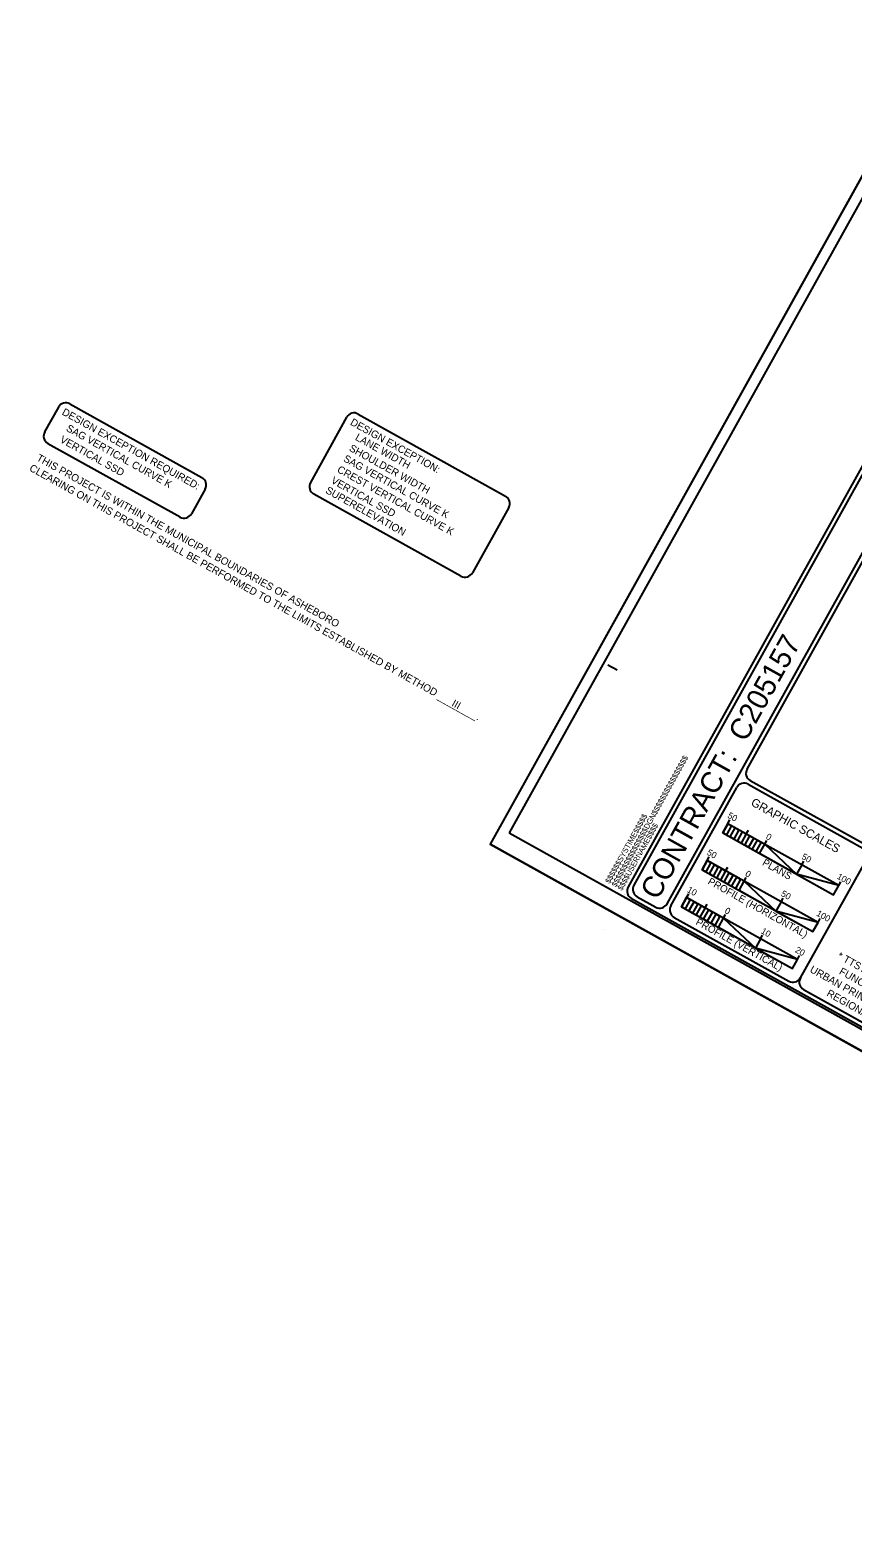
# Model space of a CAD drawing. Extents: x 1754939 to 1770240, y 706534 to 717510.
# Drawn here: x 1754939 to 1760772, y 706828 to 717510 of the extents above; entities that cross this region are included whole.
import ezdxf

# ---------------------------------------------------------------- set-up
doc = ezdxf.new("R2010")
doc.units = 0
for name, color, linetype in [('Culvert Barrel', 7, 'Continuous'), ('Culvert Wing', 7, 'Continuous'), ('Old_Level_3', 7, 'Continuous'), ('Prop Conc Drive Radius Type', 7, 'Continuous'), ('Prop Lane Arrow CELL', 7, 'Continuous'), ('Prop SS Fill Line', 7, 'Continuous'), ('Prop Superelevation  Arrow CELL', 7, 'Continuous'), ('Scratch_Level_3', 7, 'Continuous')]:
    doc.layers.add(name, color=color, linetype=linetype)

msp = doc.modelspace()

# ---------------------------------------------------------------- linework, layer by layer
at = {"layer": 'Culvert Barrel'}
for p, q in [((1761412, 717510), (1758201, 711744)), ((1758201, 711744), (1767029, 706828)), ((1767026, 706830), (1758201, 711744))]:
    msp.add_line(p, q, dxfattribs=at)
at = {"layer": 'Culvert Wing'}
msp.add_lwpolyline([(1770240, 712594), (1761412, 717510), (1758201, 711744), (1767029, 706828)], close=True, dxfattribs=at)
at = {"layer": 'Old_Level_3'}
for p, q in [((1755140, 714839), (1755042, 714664)), ((1755221, 714862), (1756157, 714341)), ((1757183, 714767), (1756926, 714306)), ((1757265, 714790), (1758309, 714209)), ((1755065, 714582), (1756002, 714061)), ((1756181, 714259), (1756083, 714084)), ((1756950, 714224), (1757993, 713643)), ((1758332, 714128), (1758075, 713666))]:
    msp.add_line(p, q, dxfattribs=at)
for centre, start, end in [((1755192, 714810), 60.8875, 150.8875), ((1757236, 714738), 60.8875, 150.8875), ((1755095, 714635), 150.8875, 240.8875), ((1756128, 714288), 330.8875, 60.8875), ((1756979, 714276), 150.8875, 240.8875), ((1758280, 714157), 330.8875, 60.8875), ((1756031, 714113), 240.8875, 330.8875), ((1758023, 713695), 240.8875, 330.8875)]:
    msp.add_arc(centre, 60, start, end, dxfattribs=at)
at = {"layer": 'Prop Conc Drive Radius Type'}
for p, q in [((1759455, 711320), (1762433, 716667)), ((1760022, 712275), (1762459, 716652)), ((1759035, 713014), (1759101, 712977)), ((1760045, 712194), (1767489, 708049)), ((1759482, 711305), (1759949, 712144)), ((1760030, 712167), (1760843, 711715)), ((1759885, 711888), (1759849, 711823)), ((1759885, 711888), (1759900, 711915)), ((1759885, 711888), (1759885, 711888)), ((1760672, 711451), (1759885, 711888)), ((1759900, 711915), (1759900, 711915)), ((1759849, 711823), (1760635, 711385)), ((1760016, 711815), (1760031, 711842)), ((1760069, 711786), (1760032, 711721)), ((1760147, 711742), (1760162, 711769)), ((1759739, 711626), (1759754, 711653)), ((1759754, 711653), (1759754, 711653)), ((1759739, 711626), (1759703, 711561)), ((1759703, 711561), (1760489, 711123)), ((1759739, 711626), (1759739, 711626)), ((1760526, 711189), (1759739, 711626)), ((1759870, 711553), (1759885, 711580)), ((1760409, 711597), (1760373, 711531)), ((1760866, 711633), (1760399, 710795)), ((1760409, 711597), (1760424, 711623)), ((1759923, 711524), (1759886, 711459)), ((1760001, 711480), (1760016, 711507)), ((1760635, 711385), (1760672, 711451)), ((1760672, 711451), (1760686, 711477)), ((1759150, 711388), (1759150, 711388)), ((1759593, 711364), (1759557, 711299)), ((1759593, 711364), (1759608, 711390)), ((1759593, 711364), (1759593, 711364)), ((1760380, 710926), (1759593, 711364)), ((1759608, 711390), (1759608, 711390)), ((1759724, 711291), (1759739, 711317)), ((1760263, 711334), (1760227, 711269)), ((1760263, 711334), (1760278, 711361)), ((1759557, 711299), (1760343, 710861)), ((1759777, 711262), (1759740, 711197)), ((1759855, 711218), (1759870, 711244)), ((1760526, 711189), (1760540, 711215)), ((1760489, 711123), (1760526, 711189)), ((1760117, 711072), (1760081, 711007)), ((1760117, 711072), (1760132, 711099)), ((1760343, 710861), (1760380, 710926)), ((1760380, 710926), (1760394, 710953))]:
    msp.add_line(p, q, dxfattribs=at)
for points in [[(1762185, 716839), (1759179, 711440)], [(1762197, 716798), (1759220, 711452)], [(1759202, 711358), (1766960, 707038)], [(1759243, 711370), (1759374, 711297)], [(1759505, 711224), (1760317, 710772)], [(1760422, 710713), (1761182, 710290)]]:
    msp.add_lwpolyline(points, dxfattribs=at)
for points in [[(1759885, 711888), (1759911, 711874), (1759875, 711808), (1759849, 711823)], [(1759938, 711859), (1759964, 711845), (1759927, 711779), (1759901, 711794)], [(1759990, 711830), (1760016, 711815), (1759980, 711750), (1759954, 711765)], [(1760042, 711801), (1760069, 711786), (1760032, 711721), (1760006, 711735)], [(1760095, 711772), (1760121, 711757), (1760085, 711692), (1760058, 711706)], [(1760147, 711742), (1760373, 711531), (1760111, 711677)], [(1759739, 711626), (1759765, 711612), (1759729, 711546), (1759703, 711561)], [(1759792, 711597), (1759818, 711583), (1759781, 711517), (1759755, 711532)], [(1759844, 711568), (1759870, 711553), (1759834, 711488), (1759808, 711502)], [(1759896, 711539), (1759923, 711524), (1759886, 711459), (1759860, 711473)], [(1760672, 711451), (1760373, 711531), (1760635, 711385)], [(1759949, 711510), (1759975, 711495), (1759939, 711429), (1759912, 711444)], [(1760001, 711480), (1760227, 711269), (1759965, 711415)], [(1759593, 711364), (1759619, 711350), (1759583, 711284), (1759557, 711299)], [(1759646, 711335), (1759672, 711320), (1759635, 711255), (1759609, 711270)], [(1759698, 711306), (1759724, 711291), (1759688, 711226), (1759662, 711240)], [(1759751, 711277), (1759777, 711262), (1759740, 711197), (1759714, 711211)], [(1759803, 711247), (1759829, 711233), (1759793, 711167), (1759767, 711182)], [(1759855, 711218), (1760081, 711007), (1759819, 711153)], [(1760526, 711189), (1760227, 711269), (1760489, 711123)], [(1760380, 710926), (1760081, 711007), (1760343, 710861)]]:
    msp.add_lwpolyline(points, close=True, dxfattribs=at)
for centre, start, end in [((1760074, 712246), 150.8875, 240.8875), ((1760001, 712115), 60.8875, 150.8875), ((1759231, 711411), 150.8875, 240.8875), ((1759272, 711423), 150.8875, 240.8875), ((1759403, 711350), 240.8875, 330.8875), ((1759534, 711277), 150.8875, 240.8875), ((1760347, 710824), 240.8875, 330.8875), ((1760452, 710766), 150.8875, 240.8875)]:
    msp.add_arc(centre, 60, start, end, dxfattribs=at)
at = {"layer": 'Prop Lane Arrow CELL'}
msp.add_lwpolyline([(1758335, 711824), (1767071, 706959), (1770151, 712490), (1761415, 717354), (1758335, 711824)], dxfattribs=at)
at = {"layer": 'Prop SS Fill Line'}
msp.add_line((1759008, 711140), (1759008, 711140), dxfattribs=at)
at = {"layer": 'Scratch_Level_3'}
for p, q in [((1759885, 711889), (1759900, 711915)), ((1760016, 711815), (1760031, 711842)), ((1760410, 711597), (1760424, 711623)), ((1760672, 711451), (1760686, 711477)), ((1759150, 711387), (1759150, 711387))]:
    msp.add_line(p, q, dxfattribs=at)

# ---------------------------------------------------------------- texts
at = {"layer": 'Prop Conc Drive Radius Type'}
for s, height, rotation, p in [('CONTRACT:  C205157', 150, 60.8875, (1759388, 711340)), ('$$$$$$$$$$$$$$$$DGN$$$$$$$$$$$$$$$$', 39.37, 60.8875, (1759093, 711436)), ('GRAPHIC SCALES', 60, 330.8875, (1760044, 712021)), ('$$$$$$SYSTIME$$$$$', 39.37, 60.8875, (1759048, 711460)), ('$$$$USERNAME$$$$', 39.37, 60.8875, (1759135, 711411)), ('0', 45, 330.8875, (1760151, 711783)), ('PLANS', 51, 330.8875, (1760125, 711597)), ('0', 45, 330.8875, (1760005, 711521)), ('0', 45, 330.8875, (1760004, 711520)), ('PROFILE (HORIZONTAL)', 51, 330.8875, (1759739, 711464)), ('PROFILE (VERTICAL)', 51, 330.8875, (1759653, 711177)), ('0', 45, 330.8875, (1759859, 711259)), ('0', 45, 330.8875, (1759859, 711258))]:
    msp.add_text(s, height=height, rotation=rotation, dxfattribs=at).set_placement(p)
at = {"layer": 'Prop Superelevation  Arrow CELL'}
for s, p in [('DESIGN EXCEPTION REQUIRED: ', (1755160, 714789)), ('DESIGN EXCEPTION: ', (1757204, 714717)), ('VERTICAL SSD', (1755146, 714594)), ('SAG VERTICAL CURVE K', (1755190, 714674)), ('LANE WIDTH', (1757239, 714610)), ('SHOULDER WIDTH', (1757196, 714533)), ('CREST VERTICAL CURVE K', (1757111, 714382)), ('SAG VERTICAL CURVE K', (1757155, 714459)), ('VERTICAL SSD', (1757068, 714304)), ('SUPERELEVATION', (1757029, 714234))]:
    msp.add_text(s, height=52.5, rotation=330.8826, dxfattribs=at).set_placement(p)
at = {"layer": 'Scratch_Level_3'}
for s, height, rotation, p in [('CLEARING ON THIS PROJECT SHALL BE PERFORMED TO THE LIMITS ESTABLISHED BY METHOD ________.', 52.5, 330.8877, (1754929, 714392)), ('THIS PROJECT IS WITHIN THE MUNICIPAL BOUNDARIES OF ASHEBORO', 52.5, 330.8877, (1754980, 714464)), ('III', 52.5, 330.8877, (1757923, 712725)), ('50', 45, 330.8875, (1759879, 711933)), ('50', 45, 330.8875, (1759733, 711671)), ('50', 45, 330.8875, (1760404, 711641)), ('100', 45, 330.8875, (1760655, 711501)), ('10', 45, 330.8875, (1759592, 711406)), ('50', 45, 330.8875, (1760258, 711379)), ('100', 45, 330.8875, (1760509, 711239)), ('10', 45, 330.8875, (1760116, 711114)), ('20 ', 45, 330.8875, (1760358, 710980)), ('* TTST =1%', 52.5, 330.8875, (1760657, 710936)), ('URBAN PRINCIPAL ARTERIAL', 52.5, 330.8875, (1760462, 710840)), ('FUNC CLASS =', 52.5, 330.8875, (1760670, 710826)), ('REGIONAL TIER', 52.5, 330.8875, (1760581, 710671))]:
    msp.add_text(s, height=height, rotation=rotation, dxfattribs=at).set_placement(p)

doc.saveas('drawing.dxf')
